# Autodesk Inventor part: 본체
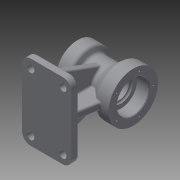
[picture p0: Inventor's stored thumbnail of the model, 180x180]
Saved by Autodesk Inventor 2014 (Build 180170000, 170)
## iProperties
Created: 2015-08
Part Number: 본체
Material: 일반
Document SubType Name: Modeling
Designer: SEC
Density: 1 g/cm^3
Appearance: 기본값
Author: SEC
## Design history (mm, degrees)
sketch "스케치1"
  geometry: L1 (0, 0)-(90, 0); L2 (90, 0)-(90, 40); L3 (90, 40)-(70, 40); L4 (70, 40)-(53.315, 26); L5 (53.315, 26)-(25.196, 26); L6 (25.196, 26)-(20, 35); L7 (20, 35)-(0, 35); L8 (0, 35)-(0, 0)
  constraints: 16 end point, 4 parallel, 1 horizontal, 1 perpendicular
  dimensions: "d8" = 90 distance of L1.start L1.end; "d9" = 20 distance of L6.end L7.end; "d10" = 20 distance of L2.end L3.end; "d11" = 60 deg angle of L5 L6; "d13" = 70 diameter of L7 L1; "d14" = 52 diameter of L5 L1; "d15" = 80 diameter of L3 L1; "d16" = 40 deg angle of L5 L4
revolve "회전1" sketch "스케치1" stored, may be unused: angle "d17" = 90 deg
sketch "스케치2"
  geometry: L1 (0, 0)-(0, -90); L2 (0, -90)-(61, -90); L3 (61, -90)-(61, -78); L4 (61, -78)-(-61, -78); L5 (-61, -78)-(-61, -90); L6 (-61, -90)-(0, -90); C1 r 35 at (0, 0) reference
  constraints: 12 end point, 3 perpendicular, 1 parallel, 1 vertical
  dimensions: "d18" = 90 distance of L1.start L1.end; "d19" = 61 distance of L1.end L2.end; "d20" = 12 distance of L2.end L3.end; "d21" = 122 distance of L3.end L4.end; "d22" = 12 distance of L4.end L5.end
extrude "돌출1" join sketch "스케치2" distance "d23" = 80; taper "d24" = 0 deg
node "작업 평면1"
sketch "스케치3"
  geometry: L1 (61, -78)-(61, -90) reference; L2 (61, -90)-(-61, -90) reference; L3 (-61, -90)-(-61, -78) reference; L4 (-61, -78)-(61, -78) reference; L5 (61, -78)-(61, -90) reference; L6 (61, -90)-(-61, -90) reference; L7 (-61, -90)-(-61, -78) reference; L8 (-61, -78)-(61, -78) reference; L9 (-51, -78)-(-23.638, -2.825); L10 (-51, -78)-(29, -78); L11 (61, -90)-(51, -90); L12 (51, -78)-(23.638, -2.825); L13 (51, -78)-(131, -78); L14 (23.638, -2.825)-(11.975, -18.945); L15 (11.975, -18.945)-(-10.369, -18.945); L16 (-10.369, -18.945)-(-23.638, -2.825); L17 (-51, -78)-(-46.794, -83.109); L18 (-46.794, -83.109)-(36.962, -83.109); L19 (36.962, -83.109)-(51, -78); C1 r 26 at (0, 0) reference; C2 r 26 at (0, 0) reference; 1 further point
  constraints: 22 end point, 4 point on line, 3 parallel, 2 equal length, 2 horizontal, 1 perpendicular
  dimensions: "d26" = 80 distance of L9.start L9.end; "d27" = 70 deg angle of L10 L9; "d28" = 10 distance of L1.end L11.end; "d29" = 80 distance of L12.start L12.end; "d30" = 110 deg angle of L13 L12; "d31" = 35.8848 deg angle of L1 L14; "d32" = 39.4585 deg angle of L1 L16; "d33" = 71.05462 distance between parallel lines of L6 L15; "d34" = 6.89067 distance between parallel lines of L6 L18; "d35" = 68.90093 distance between parallel lines of L16 L17; "d36" = 3.4202 distance from line of L1.start L19; "d37" = 17.57255 distance from line of L1.start L16
extrude "돌출2" join sketch "스케치3" stored distance "d38" = 12; taper "d39" = 0 deg
node "작업 평면2"
node "작업 평면3"
sketch "스케치4"
  geometry: L1 (0, 125)-(0, 55) reference; L2 (0, 55)-(-20, 55) reference; L3 (-20, 55)-(-25.196, 64) reference; L4 (-25.196, 64)-(-34, 64) reference; L5 (-34, 64)-(-34, 12) reference; L6 (-34, 12)-(0, 12) reference; L7 (0, 12)-(0, 0) reference; L8 (0, 0)-(-80, 0) reference; L9 (-80, 0)-(-80, 12) reference; L10 (-80, 12)-(-46, 12) reference; L11 (-46, 12)-(-46, 64) reference; L12 (-46, 64)-(-53.315, 64) reference; L13 (-53.315, 64)-(-70, 50) reference; L14 (-70, 50)-(-90, 50) reference; L15 (-90, 50)-(-90, 130) reference; L16 (-90, 130)-(-70, 130) reference; L17 (-70, 130)-(-53.315, 116) reference; L18 (-53.315, 116)-(-25.196, 116) reference; L19 (-25.196, 116)-(-20, 125) reference; L20 (-20, 125)-(0, 125) reference; L21 (0, 0)-(-10, 0); L22 (-80, 0)-(-70, 0); L23 (-70, 13.351)-(-25, 13.351); L24 (-47.359, 73.9)-(-10, 67.94); L25 (-10, 12)-(-28.69, 4.238); L26 (-28.69, 4.238)-(-60.75, 4.238); L27 (-60.75, 4.238)-(-70, 12); L28 (-70, 12)-(-77.814, 56.316); L29 (-70, 12)-(-25, 12); L30 (-77.814, 56.316)-(-47.359, 73.9); L31 (-10, 12)-(-10, 67.94); 1 further point
  constraints: 22 end point, 4 point on line, 2 horizontal, 2 parallel, 2 perpendicular, 1 equal length
  dimensions: "d40" = 10 distance of L7.end L21.end; "d44" = 45 distance of L27.end L28.end; "d45" = 100 deg angle of L29 L28
extrude "돌출3" join sketch "스케치4" stored distance "d46" = 12; taper "d47" = 0 deg
sketch "스케치5"
  geometry: C1 r 40 at (0, 0) reference; 1 further point
  constraints: 1 coincident
hole "구멍1" sketch "스케치5" at (0, 0) diameter "d48" = 38; stored, may be unused: countersink angle "d52" = 90 deg, drill point angle "d54" = 0 deg; dims "d49" = 6, "d50" = 52, "d51" = 20, "d53" = 23
sketch "스케치6"
  geometry: C1 r 35 at (0, 0) reference; 1 further point
  constraints: 1 coincident
hole "구멍2" sketch "스케치6" at (0, 0) diameter "d55" = 32; stored, may be unused: countersink angle "d59" = 90 deg, drill point angle "d61" = 0 deg; dims "d56" = 6, "d57" = 40, "d58" = 17, "d60" = 100
chamfer "모따기1" distance "d62" = 1; stored, may be unused: second distance "d63" = 2, angle "d64" = 45 deg
fillet "모깎기1" dims "d65" = 14
fillet "모깎기2" dims "d66" = 3
fillet "모깎기3" dims "d67" = 3
fillet "모깎기4" dims "d68" = 3
fillet "모깎기5" dims "d69" = 3
fillet "모깎기6" dims "d70" = 3
fillet "모깎기7" dims "d71" = 3
fillet "모깎기8" dims "d72" = 5
fillet "모깎기9" dims "d73" = 0.3
sketch "스케치7"
  geometry: C1 r 6 at (14, 94); C2 r 6 at (66, 94); C3 r 6 at (66, 0); C4 r 6 at (14, 0); A1 r 14 centre (66, 94) between (80, 94) and (66, 108) reference; A2 r 14 centre (14, 94) between (14, 108) and (0, 94) reference; A3 r 14 centre (14, 0) between (0, 0) and (14, -14) reference; A4 r 14 centre (66, 0) between (66, -14) and (80, 0) reference; 1 further point
  constraints: 4 centre point, 4 coincident
  dimensions: "d74" = 12 diameter of C1; "d75" = 12 diameter of C2; "d76" = 12 diameter of C3; "d77" = 12 diameter of C4
extrude "돌출4" cut sketch "스케치7" distance "d78" = 14; taper "d79" = 0 deg
fillet "모깎기10" dims "d80" = 3
sketch "스케치8"
  geometry: L1 (0, 0)-(0, 33); C1 r 27 at (0, 0) reference; 1 further point
  constraints: 2 end point, 1 coincident, 1 vertical
  dimensions: "d82" = 33 distance of L1.start L1.end
hole "구멍3" sketch "스케치8" at (0, 33) diameter "d83" = 3.242; stored, may be unused: countersink angle "d87" = 90 deg, drill point angle "d89" = 118 deg; dims "d84" = 10, "d85" = 40, "d86" = 17, "d88" = 13
sketch "스케치9"
  geometry: L1 (0, 0)-(0, 27); C1 r 21 at (0, 0) reference; 1 further point
  constraints: 2 end point, 1 coincident, 1 vertical
  dimensions: "d93" = 27 distance of L1.start L1.end
hole "구멍4" sketch "스케치9" at (0, 27) diameter "d94" = 3.242; stored, may be unused: countersink angle "d98" = 90 deg, drill point angle "d100" = 118 deg; dims "d95" = 10, "d96" = 40, "d97" = 17, "d99" = 13
sketch "스케치10"
  geometry: L1 (-58, -78)-(-52.245, -78) reference; L2 (-46.716, -75)-(-9, -75) reference; L3 (-9, -27.568)-(-9, -75) reference; L4 (9, -75)-(9, -27.568) reference; L5 (9, -75)-(46.716, -75) reference; L6 (46.716, -75)-(24.856, -14.94) reference; L7 (-61, -90)-(-61, -81) reference; L8 (61, -90)-(-61, -90) reference; L9 (61, -81)-(61, -90) reference; L10 (52.245, -78)-(58, -78) reference; L11 (-24.856, -14.94)-(-46.716, -75) reference; L12 (-61, -90)-(-24, -90); L13 (58, -90)-(21, -90); L14 (-30, -60)-(-30, -54); L15 (-18, -54)-(-18, -60); L16 (0, 0)-(0, -90); L17 (18, -54)-(18, -60); L18 (30, -60)-(30, -54); C1 r 16 at (0, 0) reference; A1 r 3 centre (-58, -81) between (-58, -78) and (-61, -81) reference; A2 r 29 centre (0, 0) between (-24.856, -14.94) and (-9, -27.568) reference; A3 r 26 centre (0, 0) between (24.985, -7.194) and (-24.985, -7.194) reference; A4 r 29 centre (0, 0) between (9, -27.568) and (24.856, -14.94) reference; A5 r 3 centre (58, -81) between (61, -81) and (58, -78) reference; A6 r 6 centre (-24, -60) between (-30, -60) and (-18, -60); A7 r 6 centre (-24, -54) between (-18, -54) and (-30, -54); A8 r 6 centre (24, -54) between (30, -54) and (18, -54); A9 r 6 centre (24, -60) between (18, -60) and (30, -60)
  constraints: 14 end point, 10 point on circle, 6 symmetric about line, 4 centre point, 4 tangent, 3 point on line, 2 parallel, 1 midpoint, 6 other
  dimensions: "d104" = 37 distance of L7.start L12.end
extrude "돌출5" cut sketch "스케치10" stored distance "d115" = 30; taper "d116" = 0 deg
node "솔리드1"
pattern_circular "원형 패턴1" dims angle "d91" = 360 deg
pattern_circular "원형 패턴2" dims angle "d102" = 360 deg
node "절단 모서리 투영1"
node "절단 모서리 투영2"
node "절단 모서리 투영3"
node "절단 모서리 투영4"
